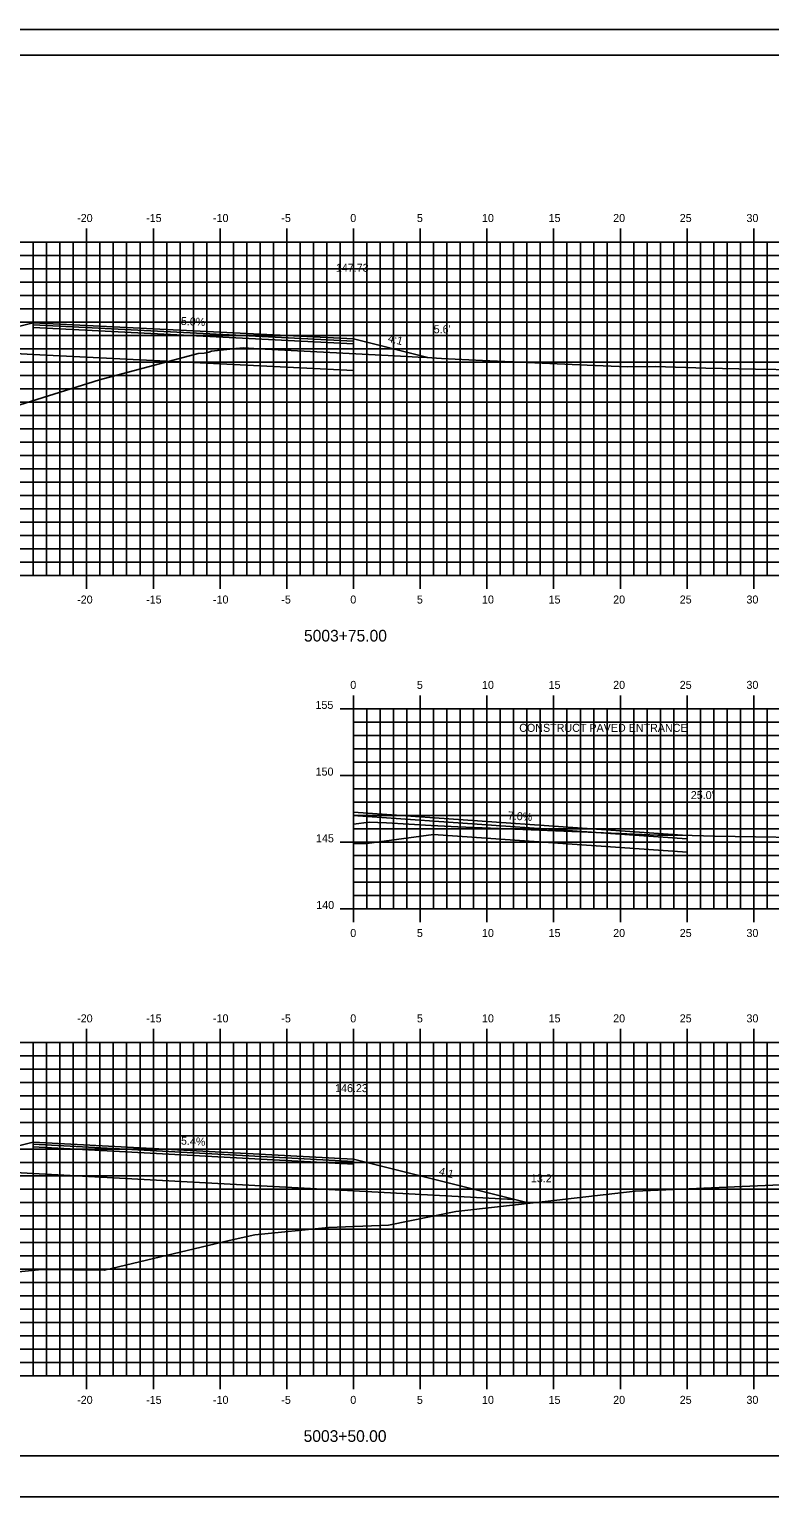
# Model space of a CAD drawing. Extents: x 851860 to 852032, y 365876 to 365986.
# Drawn here: x 851919.1 to 851974.6, y 365875.8 to 365985.8 of the extents above; entities that cross this region are included whole.
import ezdxf

# ---------------------------------------------------------------- set-up
doc = ezdxf.new("R2010")
doc.units = 0
for name, color, linetype in [('ANNOTATION', 7, 'Continuous'), ('BORDER', 7, 'Continuous'), ('D_Roadway_Centerline', 7, 'Continuous'), ('D_Roadway_Centerline_Text', 7, 'Continuous'), ('D_Roadway_Edge_TW', 7, 'Continuous'), ('D_Roadway_FinishedGrade', 7, 'Continuous'), ('D_Roadway_Pavement', 7, 'Continuous'), ('D_Roadway_SlopeLines', 7, 'Continuous'), ('D_Roadway_SubGrade', 7, 'Continuous'), ('D_Text_Standard', 7, 'Continuous'), ('H_V ANNOTATION', 7, 'Continuous'), ('MAJOR', 7, 'Continuous'), ('MINOR', 7, 'Continuous'), ('PLOT BOUNDARY', 7, 'Continuous'), ('S_Roadway_Centerline', 7, 'Continuous')]:
    doc.layers.add(name, color=color, linetype=linetype)

msp = doc.modelspace()

# ---------------------------------------------------------------- linework, layer by layer
at = {"layer": 'BORDER'}
msp.add_lwpolyline([(851868.41, 365878.83), (852028.41, 365878.83), (852028.41, 365983.83), (851868.41, 365983.83)], close=True, dxfattribs=at)
at = {"layer": 'D_Roadway_Centerline'}
for points in [[(851875.88, 365952.89), (851909.41, 365961.28), (851919.41, 365963.78), (851943.41, 365962.57), (851948.97, 365961.18)], [(851879.78, 365892.46), (851909.41, 365899.86), (851919.41, 365902.36), (851943.41, 365901.07), (851953.41, 365898.57), (851956.6, 365897.77)]]:
    msp.add_lwpolyline(points, dxfattribs=at)
at = {"layer": 'D_Roadway_Edge_TW'}
for points in [[(851919.41, 365963.78), (851943.41, 365962.57), (851943.41, 365962.4), (851919.41, 365963.61)], [(851919.41, 365902.36), (851943.41, 365901.07), (851943.41, 365900.9), (851919.41, 365902.2)]]:
    msp.add_lwpolyline(points, close=True, dxfattribs=at)
at = {"layer": 'D_Roadway_FinishedGrade'}
for p, q in [((851919.41, 365961.41), (851911.53, 365961.81)), ((851943.39, 365926.84), (851968.39, 365925.09)), ((851944.41, 365924.75), (851949.41, 365925.42)), ((851919.41, 365900), (851911.63, 365900.42)), ((851943.41, 365898.7), (851955.39, 365898.05))]:
    msp.add_line(p, q, dxfattribs=at)
for points in [[(851943.41, 365927.09), (851943.41, 365924.75), (851944.41, 365924.75)], [(851943.41, 365927.09), (851968.41, 365925.34), (851968.41, 365924.09)], [(851949.41, 365925.42), (851968.41, 365924.09)]]:
    msp.add_lwpolyline(points, dxfattribs=at)
at = {"layer": 'D_Roadway_Pavement'}
for points in [[(851919.41, 365963.61), (851943.41, 365962.4), (851943.41, 365962.2), (851919.41, 365963.41)], [(851919.41, 365902.2), (851943.41, 365900.9), (851943.41, 365900.7), (851919.41, 365902)]]:
    msp.add_lwpolyline(points, close=True, dxfattribs=at)
for points in [[(851943.41, 365962.4), (851943.41, 365962.2)], [(851943.41, 365962.4), (851943.41, 365962.2)], [(851943.41, 365926.92), (851943.41, 365926.72)], [(851943.41, 365926.92), (851943.41, 365926.72)], [(851943.41, 365900.9), (851943.41, 365900.7)], [(851943.41, 365900.9), (851943.41, 365900.7)]]:
    msp.add_lwpolyline(points, dxfattribs=at)
at = {"layer": 'D_Roadway_SlopeLines'}
for points in [[(851919.41, 365963.78), (851909.41, 365961.28), (851875.88, 365952.89)], [(851943.41, 365962.57), (851948.97, 365961.18)], [(851919.41, 365902.36), (851909.41, 365899.86), (851879.78, 365892.46)], [(851943.41, 365901.07), (851953.41, 365898.57), (851956.6, 365897.77)]]:
    msp.add_lwpolyline(points, dxfattribs=at)
at = {"layer": 'D_Roadway_SubGrade'}
for points in [[(851919.41, 365963.41), (851943.41, 365962.2), (851943.41, 365960.2), (851919.41, 365961.41)], [(851919.41, 365902), (851943.41, 365900.7)], [(851943.41, 365898.7), (851919.41, 365900)]]:
    msp.add_lwpolyline(points, dxfattribs=at)
at = {"layer": 'MAJOR'}
for p, q in [((851923.41, 365970.84), (851923.41, 365969.83)), ((851928.41, 365970.84), (851928.41, 365969.83)), ((851933.41, 365970.84), (851933.41, 365969.83)), ((851938.41, 365970.84), (851938.41, 365969.83)), ((851943.41, 365970.84), (851943.41, 365969.83)), ((851948.41, 365970.84), (851948.41, 365969.83)), ((851953.41, 365970.84), (851953.41, 365969.83)), ((851958.41, 365970.84), (851958.41, 365969.83)), ((851963.41, 365970.84), (851963.41, 365969.83)), ((851968.41, 365970.84), (851968.41, 365969.83)), ((851973.41, 365970.84), (851973.41, 365969.83)), ((851873.41, 365969.83), (852013.41, 365969.83)), ((851873.41, 365969.83), (852013.41, 365969.83)), ((851923.41, 365944.83), (851923.41, 365969.83)), ((851928.41, 365944.83), (851928.41, 365969.83)), ((851933.41, 365944.83), (851933.41, 365969.83)), ((851938.41, 365944.83), (851938.41, 365969.83)), ((851943.41, 365944.83), (851943.41, 365969.83)), ((851948.41, 365944.83), (851948.41, 365969.83)), ((851953.41, 365944.83), (851953.41, 365969.83)), ((851958.41, 365944.83), (851958.41, 365969.83)), ((851963.41, 365944.83), (851963.41, 365969.83)), ((851968.41, 365944.83), (851968.41, 365969.83)), ((851973.41, 365944.83), (851973.41, 365969.83)), ((851873.41, 365964.83), (852013.41, 365964.83)), ((851873.41, 365959.83), (852013.41, 365959.83)), ((851873.41, 365954.83), (852013.41, 365954.83)), ((851873.41, 365949.83), (852013.41, 365949.83)), ((851873.41, 365944.83), (852013.41, 365944.83)), ((851873.41, 365944.83), (852013.41, 365944.83)), ((851923.41, 365943.83), (851923.41, 365944.83)), ((851928.41, 365943.83), (851928.41, 365944.83)), ((851933.41, 365943.83), (851933.41, 365944.83)), ((851938.41, 365943.83), (851938.41, 365944.83)), ((851943.41, 365943.83), (851943.41, 365944.83)), ((851948.41, 365943.83), (851948.41, 365944.83)), ((851953.41, 365943.83), (851953.41, 365944.83)), ((851958.41, 365943.83), (851958.41, 365944.83)), ((851963.41, 365943.83), (851963.41, 365944.83)), ((851968.41, 365943.83), (851968.41, 365944.83)), ((851973.41, 365943.83), (851973.41, 365944.83)), ((851942.41, 365934.83), (851943.41, 365934.83)), ((851943.41, 365935.84), (851943.41, 365934.83)), ((851943.41, 365934.83), (852013.41, 365934.83)), ((851943.41, 365919.83), (851943.41, 365934.83)), ((851943.41, 365919.83), (851943.41, 365934.83)), ((851943.41, 365934.83), (852013.41, 365934.83)), ((851948.41, 365935.84), (851948.41, 365934.83)), ((851948.41, 365919.83), (851948.41, 365934.83)), ((851953.41, 365935.84), (851953.41, 365934.83)), ((851953.41, 365919.83), (851953.41, 365934.83)), ((851958.41, 365935.84), (851958.41, 365934.83)), ((851958.41, 365919.83), (851958.41, 365934.83)), ((851963.41, 365935.84), (851963.41, 365934.83)), ((851963.41, 365919.83), (851963.41, 365934.83)), ((851968.41, 365935.84), (851968.41, 365934.83)), ((851968.41, 365919.83), (851968.41, 365934.83)), ((851973.41, 365935.84), (851973.41, 365934.83)), ((851973.41, 365919.83), (851973.41, 365934.83)), ((851942.41, 365929.83), (851943.41, 365929.83)), ((851943.41, 365929.83), (852013.41, 365929.83)), ((851942.41, 365924.83), (851943.41, 365924.83)), ((851943.41, 365924.83), (852013.41, 365924.83)), ((851942.41, 365919.83), (851943.41, 365919.83)), ((851943.41, 365919.83), (852013.41, 365919.83)), ((851943.41, 365919.83), (852013.41, 365919.83)), ((851943.41, 365918.83), (851943.41, 365919.83)), ((851948.41, 365918.83), (851948.41, 365919.83)), ((851953.41, 365918.83), (851953.41, 365919.83)), ((851958.41, 365918.83), (851958.41, 365919.83)), ((851963.41, 365918.83), (851963.41, 365919.83)), ((851968.41, 365918.83), (851968.41, 365919.83)), ((851973.41, 365918.83), (851973.41, 365919.83)), ((851923.41, 365910.84), (851923.41, 365909.83)), ((851928.41, 365910.84), (851928.41, 365909.83)), ((851933.41, 365910.84), (851933.41, 365909.83)), ((851938.41, 365910.84), (851938.41, 365909.83)), ((851943.41, 365910.84), (851943.41, 365909.83)), ((851948.41, 365910.84), (851948.41, 365909.83)), ((851953.41, 365910.84), (851953.41, 365909.83)), ((851958.41, 365910.84), (851958.41, 365909.83)), ((851963.41, 365910.84), (851963.41, 365909.83)), ((851968.41, 365910.84), (851968.41, 365909.83)), ((851973.41, 365910.84), (851973.41, 365909.83)), ((851873.41, 365909.83), (852013.41, 365909.83)), ((851873.41, 365909.83), (852013.41, 365909.83)), ((851923.41, 365884.83), (851923.41, 365909.83)), ((851928.41, 365884.83), (851928.41, 365909.83)), ((851933.41, 365884.83), (851933.41, 365909.83)), ((851938.41, 365884.83), (851938.41, 365909.83)), ((851943.41, 365884.83), (851943.41, 365909.83)), ((851948.41, 365884.83), (851948.41, 365909.83)), ((851953.41, 365884.83), (851953.41, 365909.83)), ((851958.41, 365884.83), (851958.41, 365909.83)), ((851963.41, 365884.83), (851963.41, 365909.83)), ((851968.41, 365884.83), (851968.41, 365909.83)), ((851973.41, 365884.83), (851973.41, 365909.83)), ((851873.41, 365904.83), (852013.41, 365904.83)), ((851873.41, 365899.83), (852013.41, 365899.83)), ((851873.41, 365894.83), (852013.41, 365894.83)), ((851873.41, 365889.83), (852013.41, 365889.83)), ((851873.41, 365884.83), (852013.41, 365884.83)), ((851873.41, 365884.83), (852013.41, 365884.83)), ((851923.41, 365883.83), (851923.41, 365884.83)), ((851928.41, 365883.83), (851928.41, 365884.83)), ((851933.41, 365883.83), (851933.41, 365884.83)), ((851938.41, 365883.83), (851938.41, 365884.83)), ((851943.41, 365883.83), (851943.41, 365884.83)), ((851948.41, 365883.83), (851948.41, 365884.83)), ((851953.41, 365883.83), (851953.41, 365884.83)), ((851958.41, 365883.83), (851958.41, 365884.83)), ((851963.41, 365883.83), (851963.41, 365884.83)), ((851968.41, 365883.83), (851968.41, 365884.83)), ((851973.41, 365883.83), (851973.41, 365884.83))]:
    msp.add_line(p, q, dxfattribs=at)
at = {"layer": 'MINOR'}
for p, q in [((851919.41, 365944.83), (851919.41, 365969.83)), ((851920.41, 365944.83), (851920.41, 365969.83)), ((851921.41, 365944.83), (851921.41, 365969.83)), ((851922.41, 365944.83), (851922.41, 365969.83)), ((851924.41, 365944.83), (851924.41, 365969.83)), ((851925.41, 365944.83), (851925.41, 365969.83)), ((851926.41, 365944.83), (851926.41, 365969.83)), ((851927.41, 365944.83), (851927.41, 365969.83)), ((851929.41, 365944.83), (851929.41, 365969.83)), ((851930.41, 365944.83), (851930.41, 365969.83)), ((851931.41, 365944.83), (851931.41, 365969.83)), ((851932.41, 365944.83), (851932.41, 365969.83)), ((851934.41, 365944.83), (851934.41, 365969.83)), ((851935.41, 365944.83), (851935.41, 365969.83)), ((851936.41, 365944.83), (851936.41, 365969.83)), ((851937.41, 365944.83), (851937.41, 365969.83)), ((851939.41, 365944.83), (851939.41, 365969.83)), ((851940.41, 365944.83), (851940.41, 365969.83)), ((851941.41, 365944.83), (851941.41, 365969.83)), ((851942.41, 365944.83), (851942.41, 365969.83)), ((851944.41, 365944.83), (851944.41, 365969.83)), ((851945.41, 365944.83), (851945.41, 365969.83)), ((851946.41, 365944.83), (851946.41, 365969.83)), ((851947.41, 365944.83), (851947.41, 365969.83)), ((851949.41, 365944.83), (851949.41, 365969.83)), ((851950.41, 365944.83), (851950.41, 365969.83)), ((851951.41, 365944.83), (851951.41, 365969.83)), ((851952.41, 365944.83), (851952.41, 365969.83)), ((851954.41, 365944.83), (851954.41, 365969.83)), ((851955.41, 365944.83), (851955.41, 365969.83)), ((851956.41, 365944.83), (851956.41, 365969.83)), ((851957.41, 365944.83), (851957.41, 365969.83)), ((851959.41, 365944.83), (851959.41, 365969.83)), ((851960.41, 365944.83), (851960.41, 365969.83)), ((851961.41, 365944.83), (851961.41, 365969.83)), ((851962.41, 365944.83), (851962.41, 365969.83)), ((851964.41, 365944.83), (851964.41, 365969.83)), ((851965.41, 365944.83), (851965.41, 365969.83)), ((851966.41, 365944.83), (851966.41, 365969.83)), ((851967.41, 365944.83), (851967.41, 365969.83)), ((851969.41, 365944.83), (851969.41, 365969.83)), ((851970.41, 365944.83), (851970.41, 365969.83)), ((851971.41, 365944.83), (851971.41, 365969.83)), ((851972.41, 365944.83), (851972.41, 365969.83)), ((851974.41, 365944.83), (851974.41, 365969.83)), ((851873.41, 365968.83), (852013.41, 365968.83)), ((851873.41, 365967.83), (852013.41, 365967.83)), ((851873.41, 365966.83), (852013.41, 365966.83)), ((851873.41, 365965.83), (852013.41, 365965.83)), ((851873.41, 365963.83), (852013.41, 365963.83)), ((851873.41, 365962.83), (852013.41, 365962.83)), ((851873.41, 365961.83), (852013.41, 365961.83)), ((851873.41, 365960.83), (852013.41, 365960.83)), ((851873.41, 365958.83), (852013.41, 365958.83)), ((851873.41, 365957.83), (852013.41, 365957.83)), ((851873.41, 365956.83), (852013.41, 365956.83)), ((851873.41, 365955.83), (852013.41, 365955.83)), ((851873.41, 365953.83), (852013.41, 365953.83)), ((851873.41, 365952.83), (852013.41, 365952.83)), ((851873.41, 365951.83), (852013.41, 365951.83)), ((851873.41, 365950.83), (852013.41, 365950.83)), ((851873.41, 365948.83), (852013.41, 365948.83)), ((851873.41, 365947.83), (852013.41, 365947.83)), ((851873.41, 365946.83), (852013.41, 365946.83)), ((851873.41, 365945.83), (852013.41, 365945.83)), ((851944.41, 365919.83), (851944.41, 365934.83)), ((851945.41, 365919.83), (851945.41, 365934.83)), ((851946.41, 365919.83), (851946.41, 365934.83)), ((851947.41, 365919.83), (851947.41, 365934.83)), ((851949.41, 365919.83), (851949.41, 365934.83)), ((851950.41, 365919.83), (851950.41, 365934.83)), ((851951.41, 365919.83), (851951.41, 365934.83)), ((851952.41, 365919.83), (851952.41, 365934.83)), ((851954.41, 365919.83), (851954.41, 365934.83)), ((851955.41, 365919.83), (851955.41, 365934.83)), ((851956.41, 365919.83), (851956.41, 365934.83)), ((851957.41, 365919.83), (851957.41, 365934.83)), ((851959.41, 365919.83), (851959.41, 365934.83)), ((851960.41, 365919.83), (851960.41, 365934.83)), ((851961.41, 365919.83), (851961.41, 365934.83)), ((851962.41, 365919.83), (851962.41, 365934.83)), ((851964.41, 365919.83), (851964.41, 365934.83)), ((851965.41, 365919.83), (851965.41, 365934.83)), ((851966.41, 365919.83), (851966.41, 365934.83)), ((851967.41, 365919.83), (851967.41, 365934.83)), ((851969.41, 365919.83), (851969.41, 365934.83)), ((851970.41, 365919.83), (851970.41, 365934.83)), ((851971.41, 365919.83), (851971.41, 365934.83)), ((851972.41, 365919.83), (851972.41, 365934.83)), ((851974.41, 365919.83), (851974.41, 365934.83)), ((851943.41, 365933.83), (852013.41, 365933.83)), ((851943.41, 365933.83), (851944.41, 365933.83)), ((851943.41, 365932.83), (852013.41, 365932.83)), ((851943.41, 365932.83), (851944.41, 365932.83)), ((851943.41, 365931.83), (852013.41, 365931.83)), ((851943.41, 365931.83), (851944.41, 365931.83)), ((851943.41, 365930.83), (852013.41, 365930.83)), ((851943.41, 365930.83), (851944.41, 365930.83)), ((851943.41, 365928.83), (852013.41, 365928.83)), ((851943.41, 365928.83), (851944.41, 365928.83)), ((851943.41, 365927.83), (852013.41, 365927.83)), ((851943.41, 365927.83), (851944.41, 365927.83)), ((851943.41, 365926.83), (852013.41, 365926.83)), ((851943.41, 365926.83), (851944.41, 365926.83)), ((851943.41, 365925.83), (852013.41, 365925.83)), ((851943.41, 365925.83), (851944.41, 365925.83)), ((851943.41, 365923.83), (852013.41, 365923.83)), ((851943.41, 365923.83), (851944.41, 365923.83)), ((851943.41, 365922.83), (852013.41, 365922.83)), ((851943.41, 365922.83), (851944.41, 365922.83)), ((851943.41, 365921.83), (852013.41, 365921.83)), ((851943.41, 365921.83), (851944.41, 365921.83)), ((851943.41, 365920.83), (852013.41, 365920.83)), ((851943.41, 365920.83), (851944.41, 365920.83)), ((851919.41, 365884.83), (851919.41, 365909.83)), ((851920.41, 365884.83), (851920.41, 365909.83)), ((851921.41, 365884.83), (851921.41, 365909.83)), ((851922.41, 365884.83), (851922.41, 365909.83)), ((851924.41, 365884.83), (851924.41, 365909.83)), ((851925.41, 365884.83), (851925.41, 365909.83)), ((851926.41, 365884.83), (851926.41, 365909.83)), ((851927.41, 365884.83), (851927.41, 365909.83)), ((851929.41, 365884.83), (851929.41, 365909.83)), ((851930.41, 365884.83), (851930.41, 365909.83)), ((851931.41, 365884.83), (851931.41, 365909.83)), ((851932.41, 365884.83), (851932.41, 365909.83)), ((851934.41, 365884.83), (851934.41, 365909.83)), ((851935.41, 365884.83), (851935.41, 365909.83)), ((851936.41, 365884.83), (851936.41, 365909.83)), ((851937.41, 365884.83), (851937.41, 365909.83)), ((851939.41, 365884.83), (851939.41, 365909.83)), ((851940.41, 365884.83), (851940.41, 365909.83)), ((851941.41, 365884.83), (851941.41, 365909.83)), ((851942.41, 365884.83), (851942.41, 365909.83)), ((851944.41, 365884.83), (851944.41, 365909.83)), ((851945.41, 365884.83), (851945.41, 365909.83)), ((851946.41, 365884.83), (851946.41, 365909.83)), ((851947.41, 365884.83), (851947.41, 365909.83)), ((851949.41, 365884.83), (851949.41, 365909.83)), ((851950.41, 365884.83), (851950.41, 365909.83)), ((851951.41, 365884.83), (851951.41, 365909.83)), ((851952.41, 365884.83), (851952.41, 365909.83)), ((851954.41, 365884.83), (851954.41, 365909.83)), ((851955.41, 365884.83), (851955.41, 365909.83)), ((851956.41, 365884.83), (851956.41, 365909.83)), ((851957.41, 365884.83), (851957.41, 365909.83)), ((851959.41, 365884.83), (851959.41, 365909.83)), ((851960.41, 365884.83), (851960.41, 365909.83)), ((851961.41, 365884.83), (851961.41, 365909.83)), ((851962.41, 365884.83), (851962.41, 365909.83)), ((851964.41, 365884.83), (851964.41, 365909.83)), ((851965.41, 365884.83), (851965.41, 365909.83)), ((851966.41, 365884.83), (851966.41, 365909.83)), ((851967.41, 365884.83), (851967.41, 365909.83)), ((851969.41, 365884.83), (851969.41, 365909.83)), ((851970.41, 365884.83), (851970.41, 365909.83)), ((851971.41, 365884.83), (851971.41, 365909.83)), ((851972.41, 365884.83), (851972.41, 365909.83)), ((851974.41, 365884.83), (851974.41, 365909.83)), ((851873.41, 365908.83), (852013.41, 365908.83)), ((851873.41, 365907.83), (852013.41, 365907.83)), ((851873.41, 365906.83), (852013.41, 365906.83)), ((851873.41, 365905.83), (852013.41, 365905.83)), ((851873.41, 365903.83), (852013.41, 365903.83)), ((851873.41, 365902.83), (852013.41, 365902.83)), ((851873.41, 365901.83), (852013.41, 365901.83)), ((851873.41, 365900.83), (852013.41, 365900.83)), ((851873.41, 365898.83), (852013.41, 365898.83)), ((851873.41, 365897.83), (852013.41, 365897.83)), ((851873.41, 365896.83), (852013.41, 365896.83)), ((851873.41, 365895.83), (852013.41, 365895.83)), ((851873.41, 365893.83), (852013.41, 365893.83)), ((851873.41, 365892.83), (852013.41, 365892.83)), ((851873.41, 365891.83), (852013.41, 365891.83)), ((851873.41, 365890.83), (852013.41, 365890.83)), ((851873.41, 365888.83), (852013.41, 365888.83)), ((851873.41, 365887.83), (852013.41, 365887.83)), ((851873.41, 365886.83), (852013.41, 365886.83)), ((851873.41, 365885.83), (852013.41, 365885.83))]:
    msp.add_line(p, q, dxfattribs=at)
at = {"layer": 'PLOT BOUNDARY'}
msp.add_lwpolyline([(851860.32, 365875.77), (852030.32, 365875.77), (852030.32, 365985.77), (851860.32, 365985.77)], close=True, dxfattribs=at)
at = {"layer": 'S_Roadway_Centerline'}
for points in [[(851914.95, 365956.55), (851924.37, 365959.51), (851931.77, 365961.47), (851932.21, 365961.51), (851932.56, 365961.58), (851932.78, 365961.64), (851934.58, 365961.84), (851935.17, 365961.9), (851936.31, 365961.83), (851946.48, 365961.29), (851948.25, 365961.21), (851948.91, 365961.18), (851950, 365961.11), (851953.08, 365960.94), (851960.91, 365960.6), (851962.13, 365960.56), (851963.93, 365960.47), (851966.04, 365960.49), (851969.81, 365960.37), (851973.54, 365960.31), (851976.61, 365960.25)], [(851943.41, 365926.19), (851944.59, 365926.35), (851945.88, 365926.3), (851949.22, 365926.1), (851951.24, 365926), (851957.33, 365925.73), (851960.99, 365925.6), (851966.19, 365925.37), (851967.11, 365925.37), (851968.78, 365925.33), (851970.5, 365925.3), (851979.67, 365925.14)], [(851917.31, 365892.54), (851920.06, 365892.8), (851924.76, 365892.75), (851934.09, 365894.97), (851936.02, 365895.39), (851941.54, 365895.94), (851946.04, 365896.13), (851951.08, 365897.16), (851957.77, 365897.9), (851964.53, 365898.67), (851984.58, 365899.54), (851985.27, 365899.55), (851985.44, 365899.55), (851985.6, 365899.55), (851986.37, 365899.54), (851997.13, 365899.02), (852001.67, 365899.08), (852006.9, 365898.21), (852011.84, 365897.76), (852013.41, 365897.72)]]:
    msp.add_lwpolyline(points, dxfattribs=at)

# ---------------------------------------------------------------- texts
at = {"layer": 'ANNOTATION'}
for s, rotation, p in [('5.0%', 357.1154, (851930.46, 365963.62)), ('4:1', 345.9638, (851945.94, 365962.36)), ('7.0%', 355.996, (851954.96, 365926.55)), ('5.4%', 356.909, (851930.47, 365902.17)), ('4:1', 345.9638, (851949.76, 365899.91))]:
    msp.add_text(s, height=0.6, rotation=rotation, dxfattribs=at).set_placement(p)
msp.add_text('CONSTRUCT PAVED ENTRANCE', height=0.6, dxfattribs=at).set_placement((851955.83, 365933.11))
at = {"layer": 'D_Roadway_Centerline_Text'}
for s, p in [('147.73', (851942.09, 365967.6)), ('146.23', (851942.03, 365906.1))]:
    msp.add_text(s, height=0.6, dxfattribs=at).set_placement(p)
at = {"layer": 'D_Text_Standard'}
for s, p in [("5.6'", (851949.42, 365962.99)), ("25.0'", (851968.69, 365928.07)), ("13.2'", (851956.7, 365899.34))]:
    msp.add_text(s, height=0.6, dxfattribs=at).set_placement(p)
at = {"layer": 'H_V ANNOTATION'}
for s, height, p in [('-20', 0.6, (851922.7, 365971.33)), ('-15', 0.6, (851927.87, 365971.33)), ('-10', 0.6, (851932.88, 365971.33)), ('-5', 0.6, (851938, 365971.33)), ('0', 0.6, (851943.17, 365971.33)), ('5', 0.6, (851948.16, 365971.33)), ('10', 0.6, (851953.04, 365971.33)), ('15', 0.6, (851958.03, 365971.33)), ('20', 0.6, (851962.87, 365971.33)), ('25', 0.6, (851967.86, 365971.33)), ('30', 0.6, (851972.86, 365971.33)), ('-20', 0.6, (851922.7, 365942.73)), ('-15', 0.6, (851927.87, 365942.73)), ('-10', 0.6, (851932.88, 365942.73)), ('-5', 0.6, (851938, 365942.73)), ('0', 0.6, (851943.17, 365942.73)), ('5', 0.6, (851948.16, 365942.73)), ('10', 0.6, (851953.04, 365942.73)), ('15', 0.6, (851958.03, 365942.73)), ('20', 0.6, (851962.87, 365942.73)), ('25', 0.6, (851967.86, 365942.73)), ('30', 0.6, (851972.86, 365942.73)), ('5003+75.00', 0.875, (851939.7, 365939.88)), ('0', 0.6, (851943.17, 365936.33)), ('5', 0.6, (851948.16, 365936.33)), ('10', 0.6, (851953.04, 365936.33)), ('15', 0.6, (851958.03, 365936.33)), ('20', 0.6, (851962.87, 365936.33)), ('25', 0.6, (851967.86, 365936.33)), ('30', 0.6, (851972.86, 365936.33)), ('155', 0.6, (851940.56, 365934.83)), ('150', 0.6, (851940.57, 365929.83)), ('145', 0.6, (851940.6, 365924.83)), ('140', 0.6, (851940.62, 365919.83)), ('0', 0.6, (851943.17, 365917.73)), ('5', 0.6, (851948.16, 365917.73)), ('10', 0.6, (851953.04, 365917.73)), ('15', 0.6, (851958.03, 365917.73)), ('20', 0.6, (851962.87, 365917.73)), ('25', 0.6, (851967.86, 365917.73)), ('30', 0.6, (851972.86, 365917.73)), ('-20', 0.6, (851922.7, 365911.33)), ('-15', 0.6, (851927.87, 365911.33)), ('-10', 0.6, (851932.88, 365911.33)), ('-5', 0.6, (851938, 365911.33)), ('0', 0.6, (851943.17, 365911.33)), ('5', 0.6, (851948.16, 365911.33)), ('10', 0.6, (851953.04, 365911.33)), ('15', 0.6, (851958.03, 365911.33)), ('20', 0.6, (851962.87, 365911.33)), ('25', 0.6, (851967.86, 365911.33)), ('30', 0.6, (851972.86, 365911.33)), ('-20', 0.6, (851922.7, 365882.73)), ('-15', 0.6, (851927.87, 365882.73)), ('-10', 0.6, (851932.88, 365882.73)), ('-5', 0.6, (851938, 365882.73)), ('0', 0.6, (851943.17, 365882.73)), ('5', 0.6, (851948.16, 365882.73)), ('10', 0.6, (851953.04, 365882.73)), ('15', 0.6, (851958.03, 365882.73)), ('20', 0.6, (851962.87, 365882.73)), ('25', 0.6, (851967.86, 365882.73)), ('30', 0.6, (851972.86, 365882.73)), ('5003+50.00', 0.875, (851939.67, 365879.88))]:
    msp.add_text(s, height=height, dxfattribs=at).set_placement(p)
at = {"layer": 'MAJOR'}
msp.add_text('-', height=0.006, dxfattribs=at).set_placement((851943.41, 365919.83))

doc.saveas('drawing.dxf')
